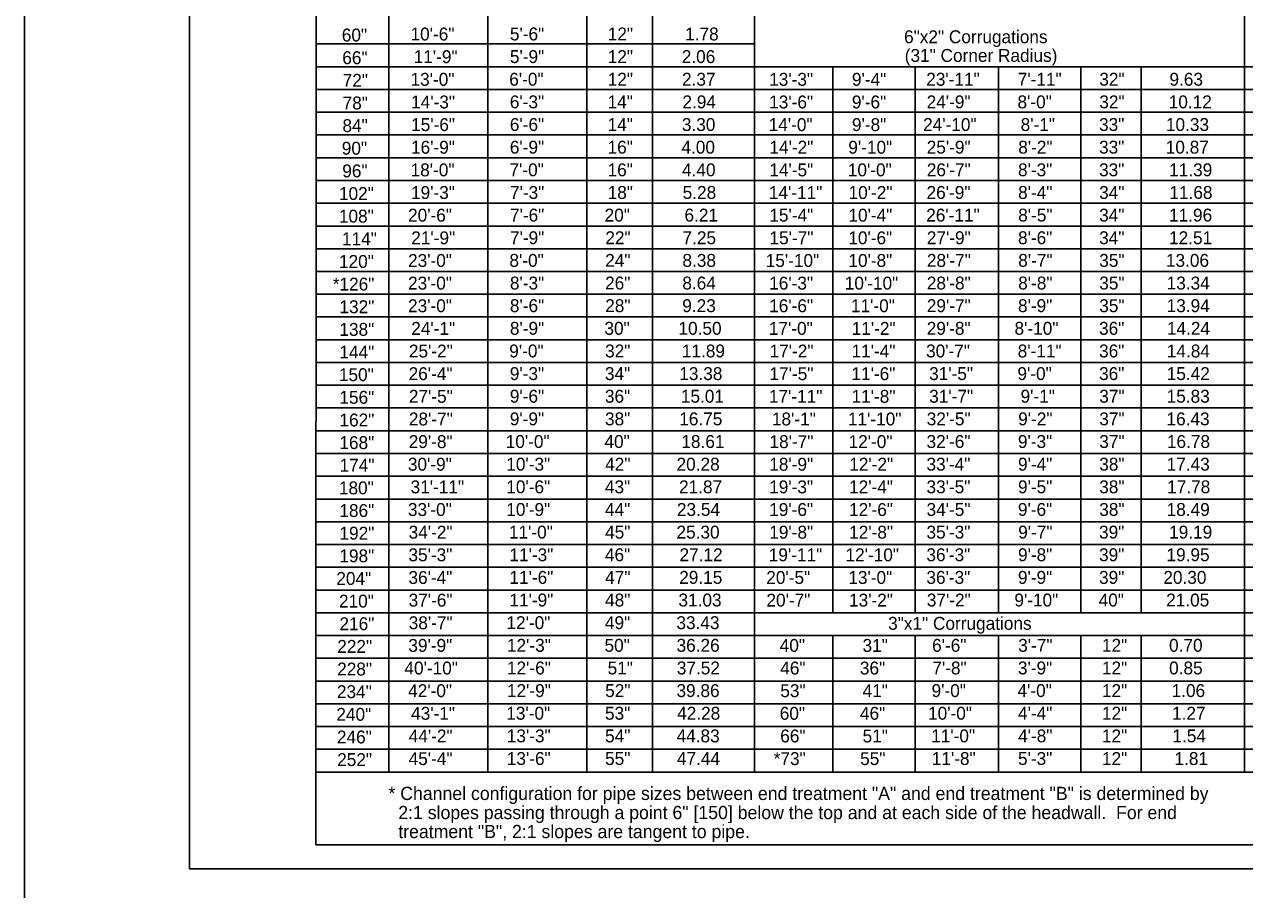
# Model space of a CAD drawing. Extents: x 1083.1 to 1117.1, y 675.4 to 741.4.
# Drawn here: x 1083.13 to 1097.9, y 719.6 to 730.07 of the extents above; entities that cross this region are included whole.
import ezdxf

# ---------------------------------------------------------------- set-up
doc = ezdxf.new("R2010")
doc.units = 0
doc.layers.add('Level 1', color=7, linetype='Continuous')

msp = doc.modelspace()

# ---------------------------------------------------------------- linework, layer by layer
at = {"layer": 'Level 1'}
for p, q in [((1086.66, 734.976), (1086.654, 720.144)), ((1091.964, 721.026), (1091.964, 734.576)), ((1097.894, 721.026), (1097.894, 734.576)), ((1087.536, 721.026), (1087.536, 734.205)), ((1088.735, 721.026), (1088.735, 734.205)), ((1089.935, 721.026), (1089.935, 734.205)), ((1090.728, 721.026), (1090.728, 734.205)), ((1091.967, 729.837), (1086.654, 729.837)), ((1091.961, 729.562), (1086.654, 729.562)), ((1091.96, 729.562), (1097.894, 729.562)), ((1092.913, 722.953), (1092.913, 729.56)), ((1093.908, 722.952), (1093.908, 729.559)), ((1094.918, 722.952), (1094.918, 729.558)), ((1095.912, 722.953), (1095.912, 729.557)), ((1096.642, 722.955), (1096.642, 729.557)), ((1103.868, 729.562), (1097.894, 729.562)), ((1103.868, 729.286), (1086.654, 729.286)), ((1103.868, 729.011), (1086.654, 729.011)), ((1103.868, 728.736), (1086.654, 728.736)), ((1103.868, 728.46), (1086.654, 728.46)), ((1103.868, 728.185), (1086.654, 728.185)), ((1103.868, 728.185), (1086.689, 728.185)), ((1103.868, 727.909), (1086.654, 727.909)), ((1103.868, 727.634), (1086.654, 727.634)), ((1103.868, 727.359), (1086.654, 727.359)), ((1103.868, 727.083), (1086.654, 727.083)), ((1103.868, 726.808), (1086.654, 726.808)), ((1103.868, 726.533), (1086.654, 726.533)), ((1103.868, 726.257), (1086.654, 726.257)), ((1103.868, 725.982), (1086.654, 725.982)), ((1103.868, 725.707), (1086.654, 725.707)), ((1103.868, 725.432), (1086.654, 725.432)), ((1103.868, 725.156), (1086.654, 725.156)), ((1103.868, 724.881), (1086.654, 724.881)), ((1103.868, 724.606), (1086.654, 724.606)), ((1103.868, 724.33), (1086.654, 724.33)), ((1103.868, 724.055), (1086.654, 724.055)), ((1103.868, 723.779), (1086.654, 723.779)), ((1103.868, 723.504), (1086.654, 723.504)), ((1103.868, 723.229), (1086.654, 723.229)), ((1103.868, 722.953), (1086.654, 722.953)), ((1097.909, 722.953), (1091.972, 722.953)), ((1103.868, 722.678), (1086.654, 722.678)), ((1091.98, 722.678), (1097.903, 722.678)), ((1092.913, 721.026), (1092.913, 722.676)), ((1093.908, 721.026), (1093.908, 722.678)), ((1094.918, 721.026), (1094.918, 722.678)), ((1095.912, 721.026), (1095.912, 722.678)), ((1096.642, 721.026), (1096.642, 722.678)), ((1103.868, 722.403), (1086.654, 722.403)), ((1103.868, 722.127), (1086.654, 722.127)), ((1103.868, 721.852), (1086.654, 721.852)), ((1103.868, 721.577), (1086.654, 721.577)), ((1103.868, 721.302), (1086.654, 721.302)), ((1086.654, 721.026), (1103.868, 721.026)), ((1086.654, 720.144), (1103.868, 720.144))]:
    msp.add_line(p, q, dxfattribs=at)
for points in [[(1083.126, 719.354), (1117.126, 719.354), (1117.126, 741.354), (1083.126, 741.354)], [(1085.126, 740.854), (1116.626, 740.854), (1116.626, 719.854), (1085.126, 719.854)]]:
    msp.add_lwpolyline(points, close=True, dxfattribs=at)

# ---------------------------------------------------------------- texts
for s, height, p in [('60"', 0.156, (1086.968, 729.867)), ('10\'-6"', 0.156, (1087.8, 729.879)), ('5\'-6"', 0.156, (1089.003, 729.88)), ('12"', 0.156, (1090.187, 729.88)), ('1.78', 0.156, (1091.124, 729.88)), ('6"x2" Corrugations', 0.156, (1093.774, 729.846)), ('66"', 0.156, (1086.974, 729.593)), ('11\'-9"', 0.156, (1087.838, 729.605)), ('5\'-9"', 0.156, (1089.003, 729.606)), ('12"', 0.156, (1090.187, 729.606)), ('2.06', 0.156, (1091.083, 729.606)), ('(31" Corner Radius)', 0.156, (1093.782, 729.62)), ('72"', 0.156, (1086.979, 729.319)), ('13\'-0"', 0.156, (1087.8, 729.331)), ('6\'-0"', 0.156, (1088.995, 729.332)), ('12"', 0.156, (1090.187, 729.332)), ('2.37', 0.156, (1091.086, 729.332)), ('13\'-3"', 0.156, (1092.141, 729.331)), ('9\'-4"', 0.156, (1093.143, 729.331)), ('23\'-11"', 0.156, (1094.042, 729.332)), ('7\'-11"', 0.156, (1095.15, 729.332)), ('32"', 0.156, (1096.137, 729.332)), ('9.63', 0.156, (1096.986, 729.332)), ('78"', 0.156, (1086.978, 729.045)), ('14\'-3"', 0.156, (1087.807, 729.057)), ('6\'-3"', 0.156, (1089.002, 729.058)), ('14"', 0.156, (1090.185, 729.058)), ('2.94', 0.156, (1091.091, 729.058)), ('13\'-6"', 0.156, (1092.141, 729.057)), ('9\'-6"', 0.156, (1093.142, 729.057)), ('24\'-9"', 0.156, (1094.047, 729.058)), ('8\'-0"', 0.156, (1095.147, 729.058)), ('32"', 0.156, (1096.137, 729.058)), ('10.12', 0.156, (1096.977, 729.058)), ('84"', 0.156, (1086.976, 728.771)), ('15\'-6"', 0.156, (1087.807, 728.783)), ('6\'-6"', 0.156, (1089.002, 728.784)), ('14"', 0.156, (1090.185, 728.784)), ('3.30', 0.156, (1091.084, 728.784)), ('14\'-0"', 0.156, (1092.135, 728.783)), ('9\'-8"', 0.156, (1093.143, 728.783)), ('24\'-10"', 0.156, (1094.004, 728.784)), ('8\'-1"', 0.156, (1095.185, 728.784)), ('33"', 0.156, (1096.134, 728.784)), ('10.33', 0.156, (1096.943, 728.784)), ('90"', 0.156, (1086.968, 728.497)), ('16\'-9"', 0.156, (1087.806, 728.509)), ('6\'-9"', 0.156, (1089.002, 728.51)), ('16"', 0.156, (1090.185, 728.51)), ('4.00', 0.156, (1091.079, 728.51)), ('14\'-2"', 0.156, (1092.144, 728.509)), ('9\'-10"', 0.156, (1093.099, 728.509)), ('25\'-9"', 0.156, (1094.048, 728.51)), ('8\'-2"', 0.156, (1095.156, 728.51)), ('33"', 0.156, (1096.134, 728.51)), ('10.87', 0.156, (1096.941, 728.51)), ('96"', 0.156, (1086.974, 728.223)), ('18\'-0"', 0.156, (1087.801, 728.235)), ('7\'-0"', 0.156, (1088.998, 728.236)), ('16"', 0.156, (1090.185, 728.236)), ('4.40', 0.156, (1091.086, 728.236)), ('14\'-5"', 0.156, (1092.143, 728.235)), ('10\'-0"', 0.156, (1093.093, 728.235)), ('26\'-7"', 0.156, (1094.049, 728.236)), ('8\'-3"', 0.156, (1095.153, 728.236)), ('33"', 0.156, (1096.134, 728.236)), ('11.39', 0.156, (1096.982, 728.236)), ('7\'-3"', 0.156, (1089.004, 727.962)), ('18"', 0.156, (1090.186, 727.962)), ('5.28', 0.156, (1091.094, 727.962)), ('26\'-9"', 0.156, (1094.046, 727.962)), ('8\'-4"', 0.156, (1095.154, 727.962)), ('34"', 0.156, (1096.135, 727.962)), ('11.68', 0.156, (1096.985, 727.962)), ('102"', 0.156, (1086.934, 727.949)), ('19\'-3"', 0.156, (1087.806, 727.961)), ('14\'-11"', 0.156, (1092.137, 727.961)), ('10\'-2"', 0.156, (1093.102, 727.961)), ('108"', 0.156, (1086.933, 727.675)), ('20\'-6"', 0.156, (1087.77, 727.687)), ('7\'-6"', 0.156, (1089.004, 727.688)), ('20"', 0.156, (1090.149, 727.688)), ('6.21', 0.156, (1091.116, 727.688)), ('15\'-4"', 0.156, (1092.143, 727.687)), ('10\'-4"', 0.156, (1093.1, 727.687)), ('26\'-11"', 0.156, (1094.042, 727.688)), ('8\'-5"', 0.156, (1095.155, 727.688)), ('34"', 0.156, (1096.135, 727.688)), ('11.96', 0.156, (1096.981, 727.688)), ('114"', 0.156, (1086.97, 727.401)), ('21\'-9"', 0.156, (1087.809, 727.413)), ('7\'-9"', 0.156, (1089.004, 727.414)), ('22"', 0.156, (1090.158, 727.414)), ('7.25', 0.156, (1091.092, 727.414)), ('15\'-7"', 0.156, (1092.145, 727.413)), ('10\'-6"', 0.156, (1093.099, 727.413)), ('27\'-9"', 0.156, (1094.049, 727.414)), ('8\'-6"', 0.156, (1095.153, 727.414)), ('34"', 0.156, (1096.135, 727.414)), ('12.51', 0.156, (1096.981, 727.414)), ('120"', 0.156, (1086.934, 727.127)), ('23\'-0"', 0.156, (1087.77, 727.139)), ('8\'-0"', 0.156, (1088.997, 727.14)), ('24"', 0.156, (1090.156, 727.14)), ('8.38', 0.156, (1091.091, 727.14)), ('15\'-10"', 0.156, (1092.099, 727.139)), ('10\'-8"', 0.156, (1093.1, 727.139)), ('28\'-7"', 0.156, (1094.05, 727.14)), ('8\'-7"', 0.156, (1095.156, 727.14)), ('35"', 0.156, (1096.136, 727.14)), ('13.06', 0.156, (1096.943, 727.14)), ('*126"', 0.156, (1086.859, 726.853)), ('23\'-0"', 0.156, (1087.77, 726.865)), ('8\'-3"', 0.156, (1089.003, 726.866)), ('26"', 0.156, (1090.155, 726.866)), ('8.64', 0.156, (1091.09, 726.866)), ('16\'-3"', 0.156, (1092.141, 726.865)), ('10\'-10"', 0.156, (1093.056, 726.865)), ('28\'-8"', 0.156, (1094.049, 726.866)), ('8\'-8"', 0.156, (1095.155, 726.866)), ('35"', 0.156, (1096.136, 726.866)), ('13.34', 0.156, (1096.952, 726.866)), ('132"', 0.156, (1086.94, 726.579)), ('23\'-0"', 0.156, (1087.77, 726.591)), ('8\'-6"', 0.156, (1089.003, 726.592)), ('28"', 0.156, (1090.156, 726.592)), ('9.23', 0.156, (1091.089, 726.592)), ('16\'-6"', 0.156, (1092.141, 726.591)), ('11\'-0"', 0.156, (1093.131, 726.591)), ('29\'-7"', 0.156, (1094.049, 726.592)), ('8\'-9"', 0.156, (1095.153, 726.592)), ('35"', 0.156, (1096.136, 726.592)), ('13.94', 0.156, (1096.952, 726.592)), ('138"', 0.156, (1086.939, 726.305)), ('24\'-1"', 0.156, (1087.809, 726.317)), ('8\'-9"', 0.156, (1089.003, 726.318)), ('30"', 0.156, (1090.147, 726.318)), ('10.50', 0.156, (1091.043, 726.318)), ('17\'-0"', 0.156, (1092.137, 726.317)), ('11\'-2"', 0.156, (1093.14, 726.317)), ('29\'-8"', 0.156, (1094.048, 726.318)), ('8\'-10"', 0.156, (1095.111, 726.318)), ('36"', 0.156, (1096.134, 726.318)), ('14.24', 0.156, (1096.955, 726.318)), ('25\'-2"', 0.156, (1087.78, 726.043)), ('9\'-0"', 0.156, (1088.995, 726.044)), ('32"', 0.156, (1090.155, 726.044)), ('11.89', 0.156, (1091.084, 726.044)), ('17\'-2"', 0.156, (1092.146, 726.043)), ('30\'-7"', 0.156, (1094.04, 726.044)), ('8\'-11"', 0.156, (1095.149, 726.044)), ('36"', 0.156, (1096.134, 726.044)), ('14.84', 0.156, (1096.954, 726.044)), ('144"', 0.156, (1086.939, 726.031)), ('11\'-4"', 0.156, (1093.138, 726.043)), ('150"', 0.156, (1086.933, 725.757)), ('26\'-4"', 0.156, (1087.777, 725.769)), ('9\'-3"', 0.156, (1089.002, 725.77)), ('34"', 0.156, (1090.153, 725.77)), ('13.38', 0.156, (1091.053, 725.77)), ('17\'-5"', 0.156, (1092.145, 725.769)), ('11\'-6"', 0.156, (1093.137, 725.769)), ('31\'-5"', 0.156, (1094.077, 725.77)), ('9\'-0"', 0.156, (1095.146, 725.77)), ('36"', 0.156, (1096.134, 725.77)), ('15.42', 0.156, (1096.953, 725.77)), ('156"', 0.156, (1086.939, 725.483)), ('27\'-5"', 0.156, (1087.78, 725.495)), ('9\'-6"', 0.156, (1089.002, 725.496)), ('36"', 0.156, (1090.153, 725.496)), ('15.01', 0.156, (1091.072, 725.496)), ('17\'-11"', 0.156, (1092.138, 725.495)), ('11\'-8"', 0.156, (1093.138, 725.495)), ('31\'-7"', 0.156, (1094.078, 725.496)), ('9\'-1"', 0.156, (1095.184, 725.496)), ('37"', 0.156, (1096.137, 725.496)), ('15.83', 0.156, (1096.952, 725.496)), ('162"', 0.156, (1086.94, 725.209)), ('28\'-7"', 0.156, (1087.78, 725.221)), ('9\'-9"', 0.156, (1089.002, 725.222)), ('38"', 0.156, (1090.154, 725.222)), ('16.75', 0.156, (1091.052, 725.222)), ('18\'-1"', 0.156, (1092.174, 725.221)), ('11\'-10"', 0.156, (1093.094, 725.221)), ('32\'-5"', 0.156, (1094.048, 725.222)), ('9\'-2"', 0.156, (1095.155, 725.222)), ('37"', 0.156, (1096.137, 725.222)), ('16.43', 0.156, (1096.95, 725.222)), ('168"', 0.156, (1086.939, 724.935)), ('29\'-8"', 0.156, (1087.778, 724.947)), ('10\'-0"', 0.156, (1088.952, 724.948)), ('40"', 0.156, (1090.147, 724.948)), ('18.61', 0.156, (1091.078, 724.948)), ('18\'-7"', 0.156, (1092.145, 724.947)), ('12\'-0"', 0.156, (1093.102, 724.947)), ('32\'-6"', 0.156, (1094.046, 724.948)), ('9\'-3"', 0.156, (1095.152, 724.948)), ('37"', 0.156, (1096.137, 724.948)), ('16.78', 0.156, (1096.955, 724.948)), ('174"', 0.156, (1086.941, 724.661)), ('30\'-9"', 0.156, (1087.768, 724.673)), ('10\'-3"', 0.156, (1088.959, 724.674)), ('42"', 0.156, (1090.156, 724.674)), ('20.28', 0.156, (1091.02, 724.674)), ('18\'-9"', 0.156, (1092.142, 724.673)), ('12\'-2"', 0.156, (1093.11, 724.673)), ('33\'-4"', 0.156, (1094.045, 724.674)), ('9\'-4"', 0.156, (1095.153, 724.674)), ('38"', 0.156, (1096.136, 724.674)), ('17.43', 0.156, (1096.952, 724.674)), ('180"', 0.156, (1086.933, 724.387)), ('31\'-11"', 0.156, (1087.801, 724.399)), ('10\'-6"', 0.156, (1088.959, 724.4)), ('43"', 0.156, (1090.153, 724.4)), ('21.87', 0.156, (1091.05, 724.4)), ('19\'-3"', 0.156, (1092.141, 724.399)), ('12\'-4"', 0.156, (1093.108, 724.399)), ('33\'-5"', 0.156, (1094.045, 724.4)), ('9\'-5"', 0.156, (1095.153, 724.4)), ('38"', 0.156, (1096.136, 724.4)), ('17.78', 0.156, (1096.958, 724.4)), ('33\'-0"', 0.156, (1087.768, 724.125)), ('10\'-9"', 0.156, (1088.959, 724.126)), ('44"', 0.156, (1090.154, 724.126)), ('23.54', 0.156, (1091.024, 724.126)), ('19\'-6"', 0.156, (1092.141, 724.125)), ('12\'-6"', 0.156, (1093.108, 724.125)), ('34\'-5"', 0.156, (1094.046, 724.126)), ('9\'-6"', 0.156, (1095.152, 724.126)), ('38"', 0.156, (1096.136, 724.126)), ('18.49', 0.156, (1096.952, 724.126)), ('186"', 0.156, (1086.939, 724.113)), ('192"', 0.156, (1086.94, 723.839)), ('34\'-2"', 0.156, (1087.777, 723.851)), ('11\'-0"', 0.156, (1088.991, 723.852)), ('45"', 0.156, (1090.155, 723.852)), ('25.30', 0.156, (1091.019, 723.852)), ('19\'-8"', 0.156, (1092.142, 723.851)), ('12\'-8"', 0.156, (1093.109, 723.851)), ('35\'-3"', 0.156, (1094.045, 723.852)), ('9\'-7"', 0.156, (1095.155, 723.852)), ('39"', 0.156, (1096.134, 723.852)), ('19.19', 0.156, (1096.982, 723.852)), ('198"', 0.156, (1086.939, 723.565)), ('35\'-3"', 0.156, (1087.775, 723.577)), ('11\'-3"', 0.156, (1088.997, 723.578)), ('46"', 0.156, (1090.153, 723.578)), ('27.12', 0.156, (1091.056, 723.578)), ('19\'-11"', 0.156, (1092.136, 723.577)), ('12\'-10"', 0.156, (1093.065, 723.577)), ('36\'-3"', 0.156, (1094.044, 723.578)), ('9\'-8"', 0.156, (1095.153, 723.578)), ('39"', 0.156, (1096.134, 723.578)), ('19.95', 0.156, (1096.95, 723.578)), ('204"', 0.156, (1086.902, 723.291)), ('36\'-4"', 0.156, (1087.775, 723.303)), ('11\'-6"', 0.156, (1088.997, 723.304)), ('47"', 0.156, (1090.156, 723.304)), ('29.15', 0.156, (1091.052, 723.304)), ('20\'-5"', 0.156, (1092.106, 723.303)), ('13\'-0"', 0.156, (1093.099, 723.303)), ('36\'-3"', 0.156, (1094.044, 723.304)), ('9\'-9"', 0.156, (1095.152, 723.304)), ('39"', 0.156, (1096.134, 723.304)), ('20.30', 0.156, (1096.912, 723.304)), ('210"', 0.156, (1086.934, 723.017)), ('37\'-6"', 0.156, (1087.777, 723.029)), ('11\'-9"', 0.156, (1088.997, 723.03)), ('48"', 0.156, (1090.155, 723.03)), ('31.03', 0.156, (1091.043, 723.03)), ('20\'-7"', 0.156, (1092.108, 723.029)), ('13\'-2"', 0.156, (1093.108, 723.029)), ('37\'-2"', 0.156, (1094.049, 723.03)), ('9\'-10"', 0.156, (1095.109, 723.03)), ('40"', 0.156, (1096.129, 723.03)), ('21.05', 0.156, (1096.946, 723.03)), ('216"', 0.156, (1086.94, 722.743)), ('38\'-7"', 0.156, (1087.778, 722.755)), ('12\'-0"', 0.156, (1088.961, 722.756)), ('49"', 0.156, (1090.153, 722.756)), ('33.43', 0.156, (1091.018, 722.756)), ('3"x1" Corrugations', 0.156, (1093.581, 722.748)), ('222"', 0.156, (1086.913, 722.469)), ('39\'-9"', 0.156, (1087.774, 722.481)), ('12\'-3"', 0.156, (1088.967, 722.482)), ('50"', 0.156, (1090.148, 722.482)), ('36.26', 0.156, (1091.02, 722.482)), ('40"', 0.156, (1092.269, 722.481)), ('31"', 0.156, (1093.271, 722.481)), ('6\'-6"', 0.156, (1094.113, 722.482)), ('3\'-7"', 0.156, (1095.155, 722.482)), ('12"', 0.156, (1096.169, 722.482)), ('0.70', 0.156, (1096.981, 722.482)), ('40\'-10"', 0.156, (1087.726, 722.207)), ('12\'-6"', 0.156, (1088.967, 722.208)), ('51"', 0.156, (1090.186, 722.208)), ('37.52', 0.156, (1091.023, 722.208)), ('46"', 0.156, (1092.275, 722.207)), ('36"', 0.156, (1093.239, 722.207)), ('7\'-8"', 0.156, (1094.116, 722.208)), ('3\'-9"', 0.156, (1095.152, 722.208)), ('12"', 0.156, (1096.169, 722.208)), ('0.85', 0.156, (1096.982, 722.208)), ('228"', 0.156, (1086.912, 722.195)), ('234"', 0.156, (1086.909, 721.921)), ('42\'-0"', 0.156, (1087.771, 721.933)), ('12\'-9"', 0.156, (1088.967, 721.934)), ('52"', 0.156, (1090.156, 721.934)), ('39.86', 0.156, (1091.019, 721.934)), ('53"', 0.156, (1092.276, 721.933)), ('41"', 0.156, (1093.272, 721.933)), ('9\'-0"', 0.156, (1094.107, 721.934)), ('4\'-0"', 0.156, (1095.147, 721.934)), ('12"', 0.156, (1096.169, 721.934)), ('1.06', 0.156, (1097.012, 721.934)), ('240"', 0.156, (1086.902, 721.647)), ('43\'-1"', 0.156, (1087.807, 721.659)), ('13\'-0"', 0.156, (1088.959, 721.66)), ('53"', 0.156, (1090.154, 721.66)), ('42.28', 0.156, (1091.027, 721.66)), ('60"', 0.156, (1092.269, 721.659)), ('46"', 0.156, (1093.24, 721.659)), ('10\'-0"', 0.156, (1094.064, 721.66)), ('4\'-4"', 0.156, (1095.153, 721.66)), ('12"', 0.156, (1096.169, 721.66)), ('1.27', 0.156, (1097.017, 721.66)), ('246"', 0.156, (1086.909, 721.373)), ('44\'-2"', 0.156, (1087.778, 721.385)), ('13\'-3"', 0.156, (1088.965, 721.386)), ('54"', 0.156, (1090.155, 721.386)), ('44.83', 0.156, (1091.02, 721.386)), ('66"', 0.156, (1092.275, 721.385)), ('51"', 0.156, (1093.272, 721.385)), ('11\'-0"', 0.156, (1094.102, 721.386)), ('4\'-8"', 0.156, (1095.154, 721.386)), ('12"', 0.156, (1096.169, 721.386)), ('1.54', 0.156, (1097.022, 721.386)), ('252"', 0.156, (1086.912, 721.099)), ('45\'-4"', 0.156, (1087.777, 721.111)), ('13\'-6"', 0.156, (1088.965, 721.112)), ('55"', 0.156, (1090.155, 721.112)), ('47.44', 0.156, (1091.024, 721.112)), ('*73"', 0.156, (1092.196, 721.111)), ('55"', 0.156, (1093.242, 721.111)), ('11\'-8"', 0.156, (1094.109, 721.112)), ('5\'-3"', 0.156, (1095.153, 721.112)), ('12"', 0.156, (1096.169, 721.112)), ('1.81', 0.156, (1097.047, 721.112)), ('* Channel configuration for pipe sizes between end treatment "A" and end treatment "B" is determined by', 0.16, (1087.533, 720.688)), ('  2:1 slopes passing through a point 6" [150] below the top and at each side of the headwall.  For end', 0.16, (1087.533, 720.457)), ('  treatment "B", 2:1 slopes are tangent to pipe.', 0.16, (1087.533, 720.227))]:
    msp.add_text(s, height=height, dxfattribs=at).set_placement(p)

doc.saveas('drawing.dxf')
